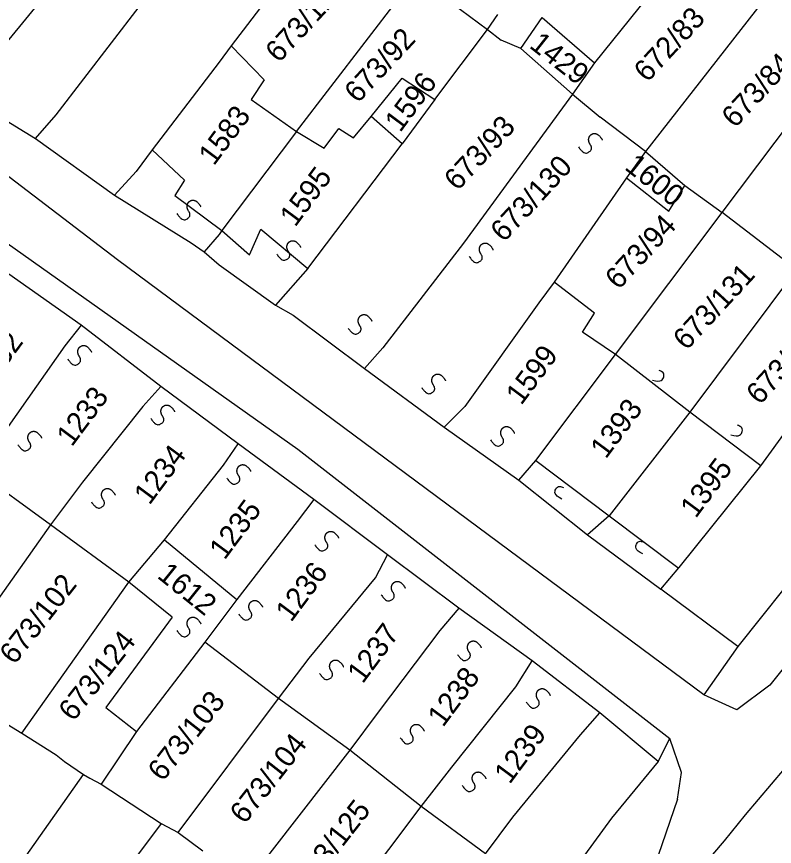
# Model space of a CAD drawing. Extents: x -581999 to -572728, y -1219553 to -1212032.
# Drawn here: x -577480.8 to -577409.5, y -1215090.1 to -1215012 of the extents above; entities that cross this region are included whole.
import ezdxf

# ---------------------------------------------------------------- set-up
doc = ezdxf.new("R2010")
doc.units = 0
for name, color, linetype in [('Vrstva 1', 7, 'Continuous'), ('Vrstva 2', 7, 'Continuous'), ('Vrstva 6', 7, 'Continuous')]:
    doc.layers.add(name, color=color, linetype=linetype)

msp = doc.modelspace()

# ---------------------------------------------------------------- linework, layer by layer
at = {"layer": 'Vrstva 1'}
for p, q in [((-577471.298, -1215034.914), (-577585.269, -1214948.007)), ((-577451.639, -1215002.977), (-577460.599, -1215014.763)), ((-577454.454, -1215022.834), (-577442.999, -1215007.889)), ((-577433.361, -1215015.021), (-577431.348, -1215012.106)), ((-577431.348, -1215012.106), (-577426.429, -1215016.367)), ((-577460.599, -1215014.763), (-577461.757, -1215016.297)), ((-577460.599, -1215014.763), (-577457.511, -1215017.96)), ((-577461.757, -1215016.297), (-577468.055, -1215024.554)), ((-577457.511, -1215017.96), (-577458.733, -1215019.824)), ((-577447.425, -1215021.4), (-577444.522, -1215017.817)), ((-577444.522, -1215017.817), (-577441.465, -1215019.824)), ((-577365.924, -1215019.323), (-577409.937, -1215074.956)), ((-577458.733, -1215019.824), (-577454.454, -1215022.834)), ((-577441.465, -1215019.824), (-577444.522, -1215023.98)), ((-577449.106, -1215023.407), (-577447.425, -1215021.4)), ((-577444.522, -1215023.98), (-577447.425, -1215021.4)), ((-577451.857, -1215024.41), (-577450.481, -1215022.547)), ((-577450.481, -1215022.547), (-577449.106, -1215023.407)), ((-577454.454, -1215022.834), (-577461.484, -1215032.15)), ((-577454.454, -1215022.834), (-577451.857, -1215024.41)), ((-577453.385, -1215035.734), (-577444.522, -1215023.98)), ((-577468.055, -1215024.554), (-577469.558, -1215026.577)), ((-577468.055, -1215024.554), (-577464.998, -1215027.42)), ((-577469.558, -1215026.577), (-577469.563, -1215026.583)), ((-577423.417, -1215027.176), (-577419.444, -1215030.329)), ((-577464.998, -1215027.42), (-577465.915, -1215028.854)), ((-577419.444, -1215030.329), (-577417.916, -1215027.893)), ((-577465.915, -1215028.854), (-577461.484, -1215032.15)), ((-577458.886, -1215034.444), (-577457.816, -1215032.007)), ((-577457.816, -1215032.007), (-577453.385, -1215035.734)), ((-577461.484, -1215032.15), (-577458.886, -1215034.444)), ((-577416.146, -1215075.842), (-577471.298, -1215034.914)), ((-577453.385, -1215035.734), (-577456.441, -1215039.174)), ((-577476.251, -1215043.006), (-577481.592, -1215050.583)), ((-577466.16, -1215068.528), (-577470.234, -1215065.255)), ((-577466.16, -1215068.528), (-577472.42, -1215077.049)), ((-577412.928, -1215071.306), (-577416.146, -1215075.842)), ((-577409.937, -1215074.956), (-577413.041, -1215077.259)), ((-577413.041, -1215077.259), (-577416.146, -1215075.842)), ((-577472.42, -1215077.049), (-577469.514, -1215079.292)), ((-577420.435, -1215082.121), (-577419.322, -1215079.966)), ((-577408.591, -1215082.805), (-577412.258, -1215087.143)), ((-577412.258, -1215087.143), (-577414.224, -1215089.606)), ((-577414.224, -1215089.606), (-577417.112, -1215092.943))]:
    msp.add_line(p, q, dxfattribs=at)
for points in [[(-577612.581, -1214947.732), (-577609.477, -1214944.72), (-577606.737, -1214943.657), (-577604.728, -1214943.303), (-577600.893, -1214944.898), (-577562.177, -1214975.018), (-577530.948, -1214998.405), (-577454.334, -1215052.718), (-577419.322, -1215079.966)], [(-577415.167, -1215002.987), (-577419.777, -1215008.071), (-577426.429, -1215016.367), (-577428.502, -1215019.322)], [(-577483.681, -1215016.774), (-577475.678, -1215007.011)], [(-577408.186, -1215007.452), (-577421.628, -1215024.715)], [(-577442.411, -1215008.799), (-577436.507, -1215013.223), (-577435.202, -1215014.217)], [(-577477.076, -1215021.259), (-577469.275, -1215011.082)], [(-577441.465, -1215019.824), (-577436.507, -1215013.223), (-577435.506, -1215011.797)], [(-577414.423, -1215030.442), (-577401.082, -1215012.766)], [(-577428.502, -1215019.322), (-577433.361, -1215015.021), (-577435.202, -1215014.217)], [(-577485.721, -1215019.416), (-577479.012, -1215023.489)], [(-577428.502, -1215019.322), (-577438.756, -1215033.338)], [(-577428.502, -1215019.322), (-577425.89, -1215021.486)], [(-577479.012, -1215023.489), (-577477.076, -1215021.259)], [(-577421.628, -1215024.715), (-577425.89, -1215021.486)], [(-577479.012, -1215023.489), (-577471.595, -1215028.805)], [(-577421.628, -1215024.715), (-577423.417, -1215027.176), (-577430.23, -1215036.998), (-577431.652, -1215038.96)], [(-577421.628, -1215024.715), (-577417.916, -1215027.893), (-577414.423, -1215030.442)], [(-577469.563, -1215026.583), (-577471.595, -1215028.805)], [(-577471.595, -1215028.805), (-577464.38, -1215033.294)], [(-577424.452, -1215043.821), (-577414.423, -1215030.442)], [(-577407.43, -1215035.818), (-577414.423, -1215030.442)], [(-577461.484, -1215032.15), (-577461.756, -1215032.513), (-577463.165, -1215034.157)], [(-577464.38, -1215033.294), (-577463.165, -1215034.157), (-577461.74, -1215035.376)], [(-577438.756, -1215033.338), (-577446.35, -1215043.203)], [(-577474.738, -1215041.049), (-577482.071, -1215035.868)], [(-577461.74, -1215035.376), (-577456.441, -1215039.174), (-577454.779, -1215040.126)], [(-577407.43, -1215035.818), (-577417.45, -1215049.236)], [(-577424.452, -1215043.821), (-577427.547, -1215041.707), (-577426.429, -1215039.913), (-577430.23, -1215036.998)], [(-577431.652, -1215038.96), (-577438.633, -1215048.726)], [(-577454.779, -1215040.126), (-577448.077, -1215045.126)], [(-577474.738, -1215041.049), (-577476.251, -1215043.006)], [(-577467.231, -1215046.822), (-577474.738, -1215041.049)], [(-577410.764, -1215054.299), (-577405.452, -1215046.957), (-577400.53, -1215041)], [(-577446.35, -1215043.203), (-577448.077, -1215045.126)], [(-577431.944, -1215053.789), (-577424.452, -1215043.821)], [(-577417.45, -1215049.236), (-577424.452, -1215043.821)], [(-577448.077, -1215045.126), (-577440.564, -1215050.648)], [(-577467.231, -1215046.822), (-577468.935, -1215048.702)], [(-577459.97, -1215052.212), (-577467.231, -1215046.822)], [(-577394.076, -1215046.12), (-577401.305, -1215056.254), (-577406.371, -1215063.07), (-577412.928, -1215071.306)], [(-577468.935, -1215048.702), (-577474.605, -1215055.828)], [(-577438.633, -1215048.726), (-577440.564, -1215050.648)], [(-577417.45, -1215049.236), (-577425.042, -1215058.996)], [(-577410.764, -1215054.299), (-577417.45, -1215049.236)], [(-577440.564, -1215050.648), (-577433.559, -1215055.649)], [(-577461.342, -1215054.234), (-577459.97, -1215052.212)], [(-577452.849, -1215057.461), (-577459.97, -1215052.212)], [(-577433.559, -1215055.649), (-577431.944, -1215053.789)], [(-577431.944, -1215053.789), (-577425.042, -1215058.996)], [(-577466.9, -1215061.248), (-577461.342, -1215054.234)], [(-577418.492, -1215063.894), (-577418.456, -1215063.852), (-577410.764, -1215054.299)], [(-577477.609, -1215059.837), (-577484.706, -1215054.704)], [(-577474.605, -1215055.828), (-577477.609, -1215059.837)], [(-577433.559, -1215055.649), (-577427.1, -1215060.803)], [(-577452.849, -1215057.461), (-577454.41, -1215059.537)], [(-577445.899, -1215062.658), (-577452.849, -1215057.461)], [(-577425.042, -1215058.996), (-577427.1, -1215060.803)], [(-577425.042, -1215058.996), (-577418.594, -1215063.879), (-577418.492, -1215063.894)], [(-577477.609, -1215059.837), (-577488.097, -1215074.653)], [(-577470.234, -1215065.255), (-577477.609, -1215059.837)], [(-577454.41, -1215059.537), (-577460.081, -1215066.886)], [(-577427.1, -1215060.803), (-577420.199, -1215065.905)], [(-577470.234, -1215065.255), (-577466.9, -1215061.248)], [(-577466.9, -1215061.248), (-577460.081, -1215066.886)], [(-577447.039, -1215064.841), (-577445.899, -1215062.658)], [(-577439.194, -1215067.692), (-577445.899, -1215062.658)], [(-577420.199, -1215065.905), (-577418.492, -1215063.894)], [(-577480.301, -1215079.469), (-577470.234, -1215065.255)], [(-577453.262, -1215072.41), (-577447.039, -1215064.841)], [(-577412.928, -1215071.306), (-577420.199, -1215065.905)], [(-577460.081, -1215066.886), (-577463.084, -1215070.895)], [(-577439.194, -1215067.692), (-577440.99, -1215069.803)], [(-577432.282, -1215072.657), (-577439.194, -1215067.692)], [(-577440.99, -1215069.803), (-577446.773, -1215077.485)], [(-577463.084, -1215070.895), (-577469.514, -1215079.292), (-577472.854, -1215084.263)], [(-577456.153, -1215076.197), (-577463.084, -1215070.895)], [(-577456.153, -1215076.197), (-577453.262, -1215072.41)], [(-577433.841, -1215075.105), (-577432.282, -1215072.657)], [(-577425.925, -1215077.546), (-577432.282, -1215072.657)], [(-577439.843, -1215082.674), (-577433.841, -1215075.105)], [(-577465.59, -1215088.807), (-577456.153, -1215076.197)], [(-577449.441, -1215081.049), (-577456.153, -1215076.197)], [(-577446.773, -1215077.485), (-577449.441, -1215081.049)], [(-577427.743, -1215079.619), (-577425.925, -1215077.546)], [(-577420.435, -1215082.121), (-577425.925, -1215077.546)], [(-577481.685, -1215078.618), (-577480.301, -1215079.469)], [(-577480.301, -1215079.469), (-577477.089, -1215081.487)], [(-577434.097, -1215087.381), (-577427.743, -1215079.619)], [(-577418.609, -1215085.665), (-577418.227, -1215083.156), (-577419.322, -1215079.966)], [(-577449.441, -1215081.049), (-577459.032, -1215093.407)], [(-577442.733, -1215086.348), (-577449.441, -1215081.049)], [(-577477.089, -1215081.487), (-577476.288, -1215082.112)], [(-577476.288, -1215082.112), (-577474.504, -1215083.34)], [(-577442.733, -1215086.348), (-577439.843, -1215082.674)], [(-577420.435, -1215082.121), (-577424.826, -1215087.45), (-577434.389, -1215100.587), (-577438.915, -1215106.531)], [(-577486.527, -1215100.347), (-577474.504, -1215083.34)], [(-577474.504, -1215083.34), (-577473.926, -1215083.695), (-577472.854, -1215084.263)], [(-577472.854, -1215084.263), (-577467.215, -1215087.954)], [(-577418.609, -1215085.665), (-577420.435, -1215090.98), (-577458.025, -1215139.972)], [(-577451.772, -1215098.371), (-577442.733, -1215086.348)], [(-577436.682, -1215090.809), (-577442.733, -1215086.348)], [(-577436.682, -1215090.809), (-577434.097, -1215087.381)], [(-577467.215, -1215087.954), (-577480.108, -1215105.218)], [(-577467.215, -1215087.954), (-577465.59, -1215088.807)], [(-577465.59, -1215088.807), (-577463.275, -1215090.528)]]:
    msp.add_lwpolyline(points, dxfattribs=at)
at = {"layer": 'Vrstva 6'}
for points, degree in [([(-577427.928, -1215024.278), (-577427.448, -1215024.985), (-577426.754, -1215024.674), (-577426.677, -1215024.274), (-577426.913, -1215023.929), (-577426.998, -1215023.597), (-577426.916, -1215023.307), (-577426.772, -1215023.127), (-577426.536, -1215022.999), (-577426.171, -1215023.035), (-577425.744, -1215023.474), (-577425.689, -1215023.647)], 2), ([(-577465.712, -1215030.558), (-577465.232, -1215031.265), (-577464.538, -1215030.954), (-577464.461, -1215030.554), (-577464.697, -1215030.209), (-577464.782, -1215029.877), (-577464.7, -1215029.587), (-577464.556, -1215029.407), (-577464.32, -1215029.279), (-577463.955, -1215029.315), (-577463.528, -1215029.754), (-577463.473, -1215029.927)], 2), ([(-577456.322, -1215034.37), (-577455.842, -1215035.077), (-577455.148, -1215034.766), (-577455.071, -1215034.366), (-577455.307, -1215034.021), (-577455.392, -1215033.689), (-577455.31, -1215033.399), (-577455.166, -1215033.219), (-577454.93, -1215033.091), (-577454.565, -1215033.127), (-577454.138, -1215033.566), (-577454.083, -1215033.739)], 2), ([(-577438.213, -1215034.594), (-577437.733, -1215035.301), (-577437.039, -1215034.99), (-577436.962, -1215034.59), (-577437.198, -1215034.245), (-577437.283, -1215033.913), (-577437.201, -1215033.623), (-577437.057, -1215033.443), (-577436.821, -1215033.315), (-577436.456, -1215033.351), (-577436.029, -1215033.79), (-577435.974, -1215033.963)], 2), ([(-577449.615, -1215041.322), (-577449.135, -1215042.029), (-577448.441, -1215041.718), (-577448.364, -1215041.318), (-577448.6, -1215040.973), (-577448.685, -1215040.641), (-577448.603, -1215040.351), (-577448.459, -1215040.171), (-577448.223, -1215040.043), (-577447.858, -1215040.079), (-577447.431, -1215040.518), (-577447.376, -1215040.691)], 2), ([(-577475.998, -1215044.237), (-577475.518, -1215044.944), (-577474.824, -1215044.633), (-577474.747, -1215044.233), (-577474.983, -1215043.888), (-577475.068, -1215043.556), (-577474.986, -1215043.266), (-577474.842, -1215043.086), (-577474.606, -1215042.958), (-577474.241, -1215042.994), (-577473.814, -1215043.433), (-577473.759, -1215043.606)], 2), ([(-577442.684, -1215046.928), (-577442.204, -1215047.635), (-577441.51, -1215047.324), (-577441.433, -1215046.924), (-577441.669, -1215046.579), (-577441.754, -1215046.247), (-577441.672, -1215045.957), (-577441.528, -1215045.777), (-577441.292, -1215045.649), (-577440.927, -1215045.685), (-577440.5, -1215046.124), (-577440.445, -1215046.297)], 2), ([(-577420.962, -1215046.223), (-577420.149, -1215046.485), (-577419.794, -1215045.813), (-577419.976, -1215045.455), (-577420.235, -1215045.369), (-577420.343, -1215045.316)], 3), ([(-577468.173, -1215049.844), (-577467.693, -1215050.551), (-577466.999, -1215050.24), (-577466.922, -1215049.84), (-577467.158, -1215049.495), (-577467.243, -1215049.163), (-577467.161, -1215048.873), (-577467.017, -1215048.693), (-577466.781, -1215048.565), (-577466.416, -1215048.601), (-577465.989, -1215049.04), (-577465.934, -1215049.213)], 2), ([(-577436.2, -1215051.862), (-577435.72, -1215052.569), (-577435.026, -1215052.258), (-577434.949, -1215051.858), (-577435.185, -1215051.513), (-577435.27, -1215051.181), (-577435.188, -1215050.891), (-577435.044, -1215050.711), (-577434.808, -1215050.583), (-577434.443, -1215050.619), (-577434.016, -1215051.058), (-577433.961, -1215051.231)], 2), ([(-577413.583, -1215051.381), (-577412.77, -1215051.643), (-577412.415, -1215050.971), (-577412.597, -1215050.613), (-577412.856, -1215050.527), (-577412.964, -1215050.474)], 3), ([(-577480.693, -1215052.31), (-577480.213, -1215053.017), (-577479.519, -1215052.706), (-577479.442, -1215052.306), (-577479.678, -1215051.961), (-577479.763, -1215051.629), (-577479.681, -1215051.339), (-577479.537, -1215051.159), (-577479.301, -1215051.031), (-577478.936, -1215051.067), (-577478.509, -1215051.506), (-577478.454, -1215051.679)], 2), ([(-577461.018, -1215055.45), (-577460.538, -1215056.157), (-577459.844, -1215055.846), (-577459.767, -1215055.446), (-577460.003, -1215055.101), (-577460.088, -1215054.769), (-577460.006, -1215054.479), (-577459.862, -1215054.299), (-577459.626, -1215054.171), (-577459.261, -1215054.207), (-577458.834, -1215054.646), (-577458.779, -1215054.819)], 2), ([(-577473.762, -1215057.693), (-577473.282, -1215058.4), (-577472.588, -1215058.089), (-577472.511, -1215057.689), (-577472.747, -1215057.344), (-577472.832, -1215057.012), (-577472.75, -1215056.722), (-577472.606, -1215056.542), (-577472.37, -1215056.414), (-577472.005, -1215056.45), (-577471.578, -1215056.889), (-577471.523, -1215057.062)], 2), ([(-577429.488, -1215057.418), (-577430.272, -1215057.077), (-577430.095, -1215056.338), (-577429.722, -1215056.191), (-577429.471, -1215056.298), (-577429.355, -1215056.329)], 3), ([(-577452.745, -1215061.729), (-577452.265, -1215062.436), (-577451.571, -1215062.125), (-577451.494, -1215061.725), (-577451.73, -1215061.38), (-577451.815, -1215061.048), (-577451.733, -1215060.758), (-577451.589, -1215060.578), (-577451.353, -1215060.45), (-577450.988, -1215060.486), (-577450.561, -1215060.925), (-577450.506, -1215061.098)], 2), ([(-577421.887, -1215062.576), (-577422.671, -1215062.235), (-577422.494, -1215061.496), (-577422.121, -1215061.349), (-577421.87, -1215061.456), (-577421.754, -1215061.487)], 3), ([(-577446.485, -1215066.439), (-577446.005, -1215067.146), (-577445.311, -1215066.835), (-577445.234, -1215066.435), (-577445.47, -1215066.09), (-577445.555, -1215065.758), (-577445.473, -1215065.468), (-577445.329, -1215065.288), (-577445.093, -1215065.16), (-577444.728, -1215065.196), (-577444.301, -1215065.635), (-577444.246, -1215065.808)], 2), ([(-577459.9, -1215068.233), (-577459.42, -1215068.94), (-577458.726, -1215068.629), (-577458.649, -1215068.229), (-577458.885, -1215067.884), (-577458.97, -1215067.552), (-577458.888, -1215067.262), (-577458.744, -1215067.082), (-577458.508, -1215066.954), (-577458.143, -1215066.99), (-577457.716, -1215067.429), (-577457.661, -1215067.602)], 2), ([(-577465.713, -1215069.803), (-577465.233, -1215070.51), (-577464.539, -1215070.199), (-577464.462, -1215069.799), (-577464.698, -1215069.454), (-577464.783, -1215069.122), (-577464.701, -1215068.832), (-577464.557, -1215068.652), (-577464.321, -1215068.524), (-577463.956, -1215068.56), (-577463.529, -1215068.999), (-577463.474, -1215069.172)], 2), ([(-577439.33, -1215072.045), (-577438.85, -1215072.752), (-577438.156, -1215072.441), (-577438.079, -1215072.041), (-577438.315, -1215071.696), (-577438.4, -1215071.364), (-577438.318, -1215071.074), (-577438.174, -1215070.894), (-577437.938, -1215070.766), (-577437.573, -1215070.802), (-577437.146, -1215071.241), (-577437.091, -1215071.414)], 2), ([(-577452.298, -1215073.839), (-577451.818, -1215074.546), (-577451.124, -1215074.235), (-577451.047, -1215073.835), (-577451.283, -1215073.49), (-577451.368, -1215073.158), (-577451.286, -1215072.868), (-577451.142, -1215072.688), (-577450.906, -1215072.56), (-577450.541, -1215072.596), (-577450.114, -1215073.035), (-577450.059, -1215073.208)], 2), ([(-577432.846, -1215076.53), (-577432.366, -1215077.237), (-577431.672, -1215076.926), (-577431.595, -1215076.526), (-577431.831, -1215076.181), (-577431.916, -1215075.849), (-577431.834, -1215075.559), (-577431.69, -1215075.379), (-577431.454, -1215075.251), (-577431.089, -1215075.287), (-577430.662, -1215075.726), (-577430.607, -1215075.899)], 2), ([(-577444.696, -1215079.894), (-577444.216, -1215080.601), (-577443.522, -1215080.29), (-577443.445, -1215079.89), (-577443.681, -1215079.545), (-577443.766, -1215079.213), (-577443.684, -1215078.923), (-577443.54, -1215078.743), (-577443.304, -1215078.615), (-577442.939, -1215078.651), (-577442.512, -1215079.09), (-577442.457, -1215079.263)], 2), ([(-577438.883, -1215084.379), (-577438.403, -1215085.086), (-577437.709, -1215084.775), (-577437.632, -1215084.375), (-577437.868, -1215084.03), (-577437.953, -1215083.698), (-577437.871, -1215083.408), (-577437.727, -1215083.228), (-577437.491, -1215083.1), (-577437.126, -1215083.136), (-577436.699, -1215083.575), (-577436.644, -1215083.748)], 2)]:
    msp.add_open_spline(points, degree=degree, dxfattribs=at)

# ---------------------------------------------------------------- texts
at = {"layer": 'Vrstva 2'}
for s, rotation, p in [('673/129', 47.27257, (-577456.123, -1215016.443)), ('672/83', 47.27257, (-577421.445, -1215018.275)), ('673/92', 47.27257, (-577448.687, -1215020.246)), ('1429', 321.70279, (-577432.655, -1215014.864)), ('673/84', 47.27257, (-577413.193, -1215022.58)), ('1596', 53.33187, (-577444.713, -1215022.987)), ('1583', 53.33187, (-577462.243, -1215026.128)), ('673/93', 47.27257, (-577439.3, -1215028.493)), ('673/130', 47.27257, (-577434.945, -1215033.326)), ('1600', 321.70279, (-577423.692, -1215026.316)), ('1595', 53.33187, (-577454.593, -1215031.894)), ('673/94', 47.27257, (-577424.15, -1215037.797)), ('673/131', 47.27257, (-577417.758, -1215043.503)), ('1232', 53.33187, (-577483.646, -1215047.405)), ('673/95', 47.27257, (-577410.874, -1215048.639)), ('1599', 53.33187, (-577433.321, -1215048.67)), ('1233', 53.33187, (-577475.607, -1215052.576)), ('1393', 53.33187, (-577425.361, -1215053.724)), ('1234', 53.33187, (-577468.302, -1215058.061)), ('1395', 53.33187, (-577416.901, -1215059.311)), ('1235', 53.33187, (-577461.229, -1215063.227)), ('1612', 321.18501, (-577467.672, -1215064.771)), ('1236', 53.33187, (-577454.976, -1215069.089)), ('673/102', 51.89165, (-577481.006, -1215073.095)), ('1237', 53.33187, (-577448.24, -1215074.881)), ('673/124', 51.89165, (-577475.452, -1215078.44)), ('1238', 53.33187, (-577440.68, -1215078.974)), ('673/103', 51.89165, (-577467.051, -1215084.1)), ('1239', 53.33187, (-577434.407, -1215084.338)), ('673/104', 51.89165, (-577459.337, -1215088.098)), ('673/125', 51.89165, (-577453.361, -1215094.344))]:
    msp.add_text(s, height=2, rotation=rotation, dxfattribs=at).set_placement(p)

doc.saveas('drawing.dxf')
